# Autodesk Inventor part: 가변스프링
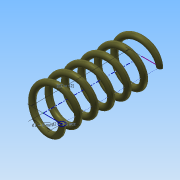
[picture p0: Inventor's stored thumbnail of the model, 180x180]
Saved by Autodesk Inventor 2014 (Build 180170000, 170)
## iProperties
Created: 2015-05
Part Number: 가변스프링
Material: 티타늄
Document SubType Name: Modeling
Designer: net
Density: 4.51 g/cm^3
Appearance: 티타늄
Mass: 6.59459 g
Surface Area: 23.7519 cm^2
Volume: 1.46221 cm^3
Author: net
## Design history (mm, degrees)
sketch "스케치1"
  geometry: L1 (0, 42)-(8, 42); L2 (8, 42)-(8, 0); L3 (8, 0)-(0, 0); L4 (0, 0)-(0, 42); C1 r 1.25 at (8, 0); 1 further point
  constraints: 8 end point, 2 coincident, 2 parallel, 1 centre point, 1 horizontal, 1 perpendicular
  dimensions: "d0" = 42 distance of L3.end L1.start (derived); "d1" = 8 distance of L2.end L3.end; "d2" = 2.5 diameter of C1
feature "코일1" sketch "스케치1" pitch "d3" = 10; turns "d5" = 6; dims "d4" = 42 (= d0), "d6" = 0, angle "d7" = 90 deg, angle "d8" = 90 deg, "d9" = 0, "d10" = 0
node "작업 평면1"
sketch "스케치2"
  geometry: L1 (6.75, 0)-(9.25, 0) reference; 1 further point
  constraints: 1 horizontal alignment
extrude "돌출1" cut sketch "스케치2" distance "d11" = 10; taper "d12" = 0 deg
node "작업 평면2"
sketch "스케치3"
  geometry: L1 (-6.75, 0)-(-9.25, 0) reference; 1 further point
  constraints: 1 horizontal alignment
extrude "돌출2" cut sketch "스케치3" distance "d13" = 10; taper "d14" = 0 deg
node "솔리드1"
node "절단 모서리 투영1"
node "절단 모서리 투영2"
